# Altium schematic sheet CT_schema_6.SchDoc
size 369 x 245 mm
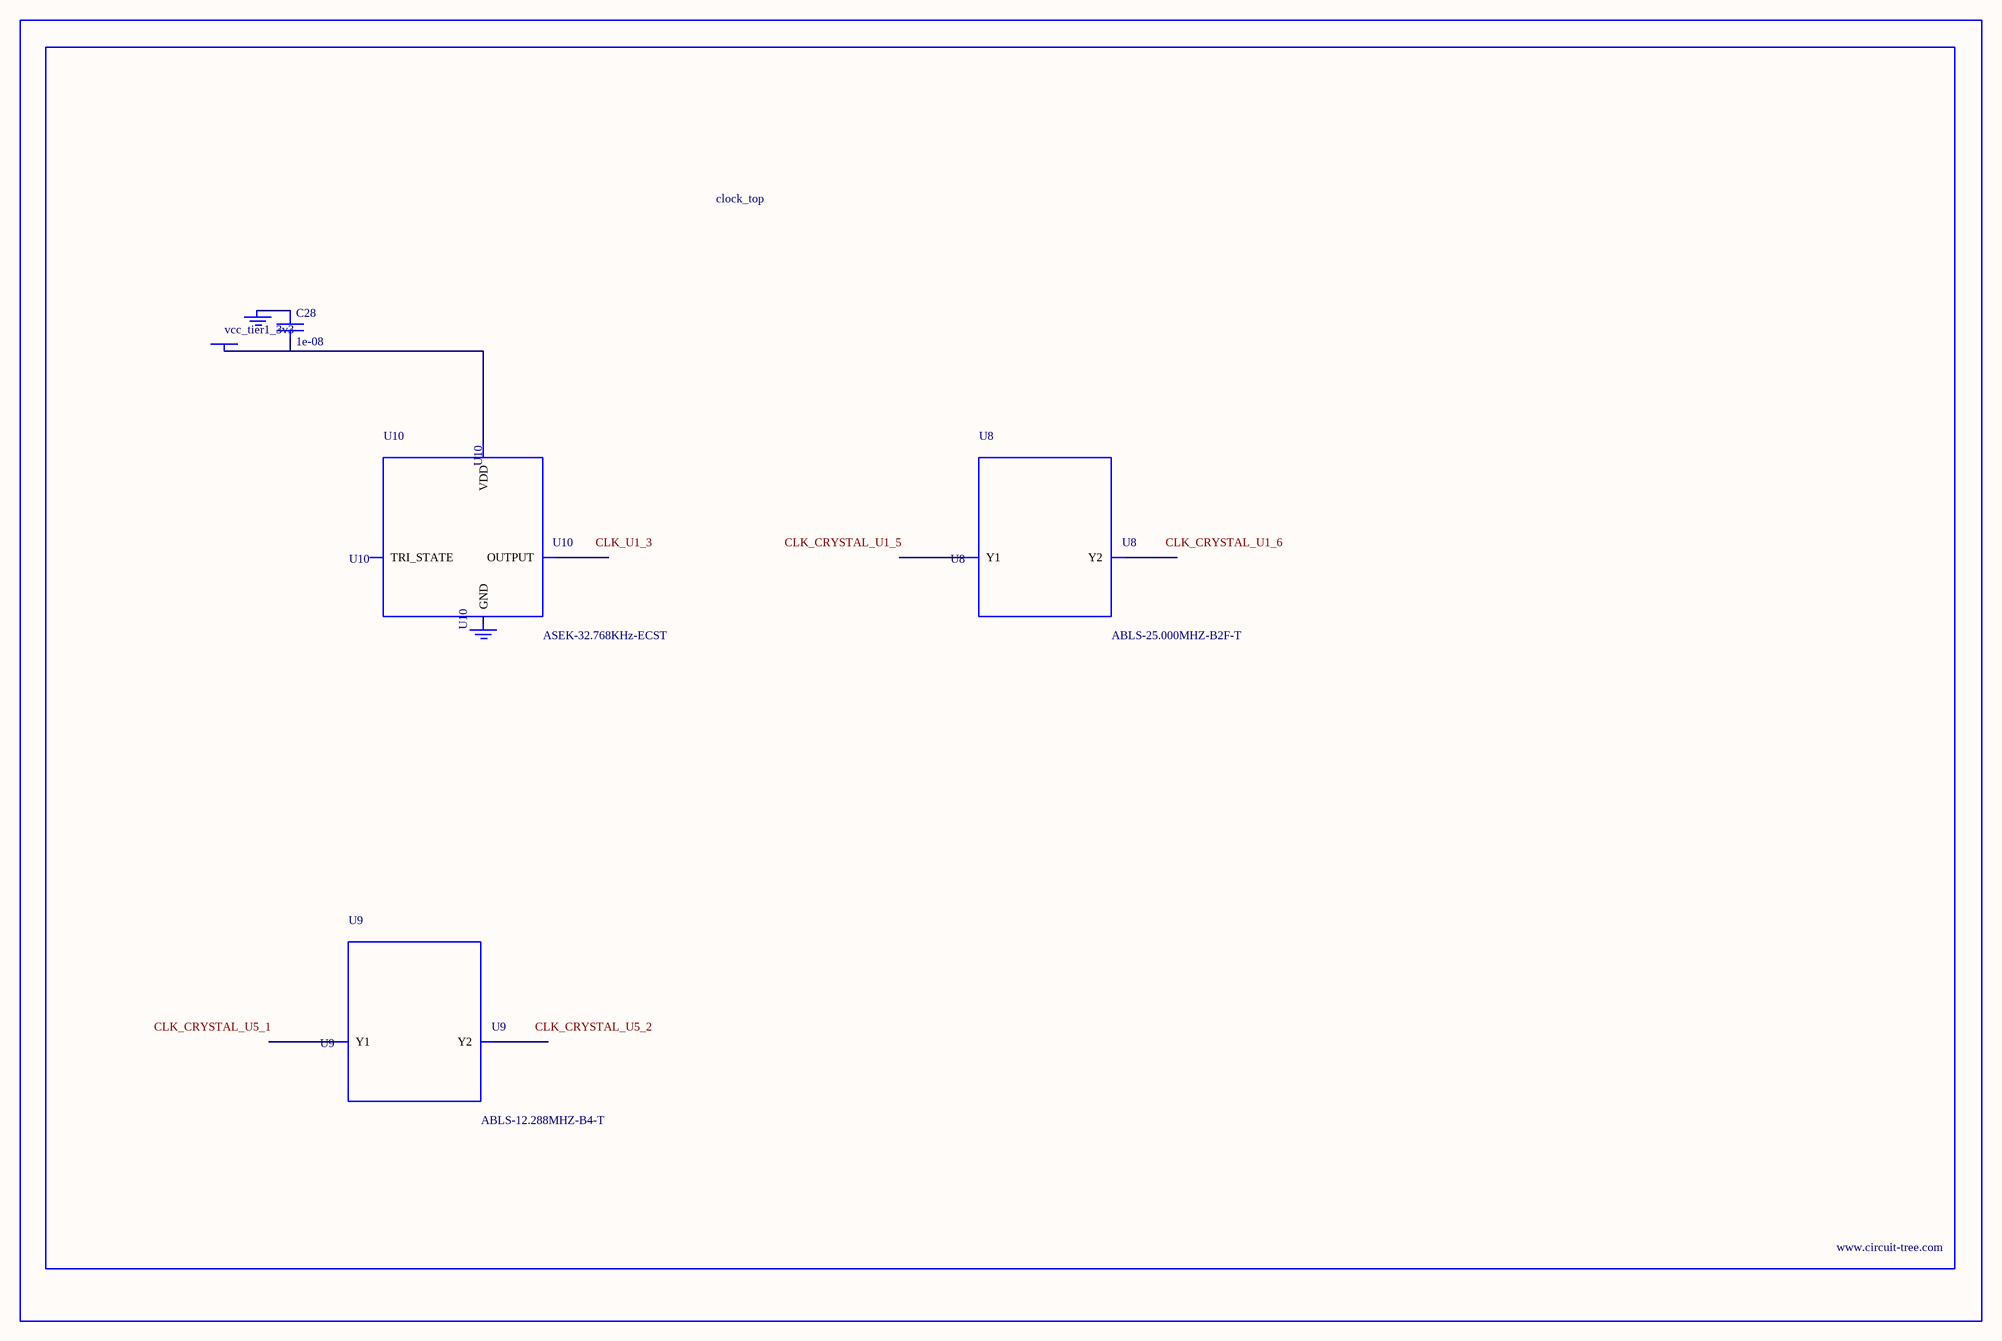
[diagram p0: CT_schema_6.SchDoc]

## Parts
BORDER5  (no value)
C28  1e-08  [C0402]
GND_INSTANCE_5_0  (no value)
GND_INSTANCE_5_1  (no value)
POWER_INSTANCE_5_0  vcc_tier1_3v3
U8  ABLS-25.000MHZ-B2F-T  [ABLS-25.000MHZ-B2F-T]
U9  ABLS-12.288MHZ-B4-T  [ABLS-12.288MHZ-B4-T]
U10  ASEK-32.768KHz-ECST  [ASEK]

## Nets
NetC28_1: C28.1 GND_INSTANCE_5_0.0(GND)
NetC28_2: C28.2 POWER_INSTANCE_5_0.0(PWR) U10.4(VDD)

Not connected (* = marked no-connect by the designer): GND_INSTANCE_5_1 0(GND); U8 1(Y1) 2(Y2); U9 1(Y1) 2(Y2); U10 1(TRI_STATE) 2(GND) 3(OUTPUT)

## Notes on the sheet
- Labels drawn without touching a wire or pin: CLK_CRYSTAL_U1_5, CLK_CRYSTAL_U1_6, CLK_CRYSTAL_U5_1, CLK_CRYSTAL_U5_2, CLK_U1_3

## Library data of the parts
BORDER5 = BORDER_PAGE5
C28 = C0402C103K3RAC
GND_INSTANCE_5_0 GND_INSTANCE_5_1 = GND
POWER_INSTANCE_5_0 = PWR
